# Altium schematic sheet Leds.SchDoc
size A4
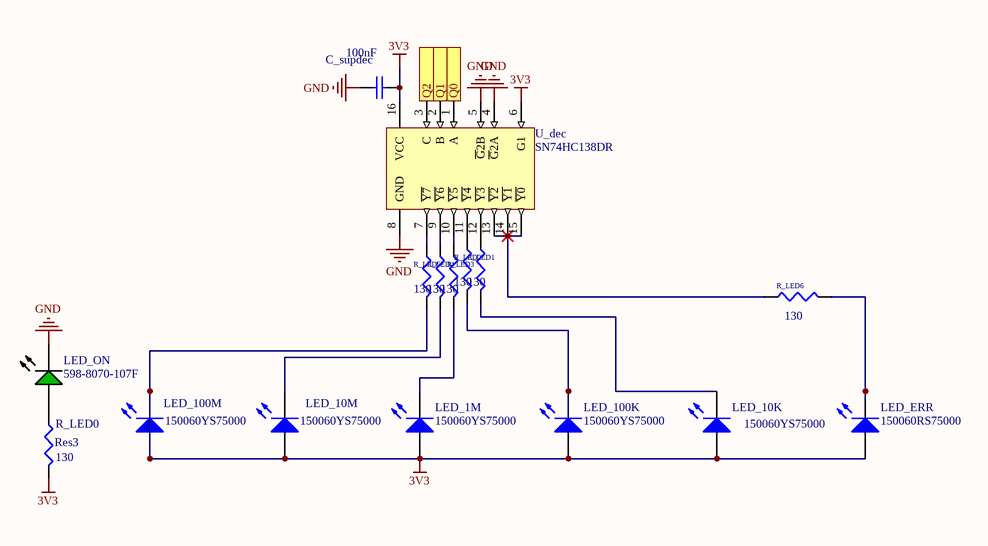
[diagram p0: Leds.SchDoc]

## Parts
C_supdec  value 100nF  [J1-0603]  (hidden comment: Cap Semi)
LED_1M  150060YS75000  [0603_A]
LED_10K  150060YS75000  [0603_A]
LED_10M  150060YS75000  [0603_A]
LED_100K  150060YS75000  [0603_A]
LED_100M  150060YS75000  [0603_A]
LED_ERR  150060RS75000  [0603_A]
LED_ON  598-8070-107F  [DIAL-0603-2_V]
R_LED0  Res3  value 130  [J1-0603]
R_LED1  value 130  [J1-0603]  (hidden comment: Res3)
R_LED2  value 130  [J1-0603]  (hidden comment: Res3)
R_LED3  value 130  [J1-0603]  (hidden comment: Res3)
R_LED4  value 130  [J1-0603]  (hidden comment: Res3)
R_LED5  value 130  [J1-0603]  (hidden comment: Res3)
R_LED6  value 130  [J1-0603]  (hidden comment: Res3)
U_dec  SN74HC138DR  [D0016A_L]

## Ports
Q0, Q1, Q2

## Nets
3V3: C_supdec.1 LED_1M.2(A) LED_10K.2(A) LED_10M.2(A) LED_100K.2(A) LED_100M.1(K) LED_100M.2(A) LED_ERR.2(A) R_LED0.2 R_LED5.2 U_dec.6(G1) U_dec.16(VCC)
GND: C_supdec.2 LED_ON.1(K) U_dec.4(~{G}2A) U_dec.5(~{G}2B) U_dec.8(GND)
Q0: U_dec.1(A) ; port Q0
Q1: U_dec.2(B) ; port Q1
Q2: U_dec.3(C) ; port Q2
NetLED_1M_1: LED_1M.1(K) R_LED3.2
NetLED_10K_1: LED_10K.1(K) R_LED1.2
NetLED_10M_1: LED_10M.1(K) R_LED4.2
NetLED_100K_1: LED_100K.1(K) R_LED2.2
NetLED_ERR_1: LED_ERR.1(K) R_LED6.2
NetLED_ON_2: LED_ON.2(A) R_LED0.1
NetR_LED1_1: R_LED1.1 U_dec.12(~{Y3})
NetR_LED2_1: R_LED2.1 U_dec.11(~{Y4})
NetR_LED3_1: R_LED3.1 U_dec.10(~{Y5})
NetR_LED4_1: R_LED4.1 U_dec.9(~{Y6})
NetR_LED5_1: R_LED5.1 U_dec.7(~{Y7})
NetR_LED6_1: R_LED6.1 U_dec.13(~{Y2}) U_dec.14(~{Y1}) U_dec.15(~{Y0})

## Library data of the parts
C_supdec = Cap Semi: Capacitor (Semiconductor SIM Model)
LED_1M LED_10K LED_10M LED_100K LED_100M = CMP-1426-00005-1: SMD mono-color Chip LED, WL-SMCW, Yellow; Manufacturer: Wuerth Elektronik
LED_ERR = CMP-1426-00001-1: SMD mono-color Chip LED, WL-SMCW, Red; Manufacturer: Wuerth Elektronik
LED_ON = CMP-2000-05654-1: Single Color LED, 2 V, -30 to 85 degC, 2-Pin SMD (0603), RoHS, Tape and Reel; Manufacturer: Dialight; Power Dissipation: 60W; DELETED: Compliant; Number of  Elements: 1; Viewing Angle: 140deg; Dominant Wave Length: 568nm; Product Depth (mm): 0.8mm; Emitting Color: YellowGreen; Main Category: ChipLED; Product Length (mm): 1.6mm; Forward Voltage: 2.4V; Luminous Intensity: 20mcd; High Brightness: No; Forward Current: 25mA; Test Current (It): 20mA; Shape Type: Rectangular; Reverse Voltage: 5V; Product Height (mm): 0.7mm; Chip Material: GaP
R_LED0-R_LED6 = Res3: Resistor
U_dec = CMP-1633-00238-2: 3-Line To 8-Line Decoders/Demultiplexers, D0016A, LARGE T&R; Manufacturer: Texas Instruments; VCC(Max)(V): 6; F @ Nom Voltage(Max)(Mhz): 28; Channels(#): 1; Technology Family: HC; VCC(Min)(V): 2; Function: Decoder/Demultiplexer; ICC @ Nom Voltage(Max)(mA): 0.08; tpd @ Nom Voltage(Max)(ns): 45; Voltage(Nom)(V): 3.3,5; Bits(#): 8; Output Type: CMOS; Input Type: LVTTL/CMOS; Schmitt Trigger: No; Configuration: 3：8; Output Drive (IOL/IOH)(Max)(mA): 5.2/-5.2; Rating: Catalog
